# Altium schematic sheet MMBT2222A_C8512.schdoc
size 127 x 101 mm
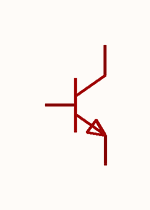
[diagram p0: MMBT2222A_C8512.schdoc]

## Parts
Q?  mmbt2222a 1p  [SOT-23-3_L2.9-W1.3-P1.90-LS2.4-BR]  (value not drawn)

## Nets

Not connected (* = marked no-connect by the designer): Q? 1(B) 2(E) 3(C)

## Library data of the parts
Q? = mmbt2222a 1p: 晶体管类型:NPN;集电极电流(Ic):600mA;集射极击穿电压(Vceo):40V;耗散功率(Pd):300mW;直流电流增益(hFE):100;; Manufacturer: CJ(江苏长电/长晶); Symbol: MMBT2222A_C8512; AddInBom: yes; ModelId: c62791f0466c4ae2a892c056b845b0ca; ModelName: SOT-23-3P_L2.9-W1.3-H1.0-LS2.4-P0.95; ModelTransform: 98.425,114.173,0,180,0,0,0.0005,-0.0005,0; type: NPN; Current - Collector(Ic): 600mA; Collector - Emitter Voltage VCEO: 40V; Pd - Power Dissipation: 300mW; DC Current Gain: 100; Transition frequency(fT): 300MHz; Current - Collector Cutoff: 10nA; Emitter-Base Voltage(Vebo): 6V; Number: 1个NPN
